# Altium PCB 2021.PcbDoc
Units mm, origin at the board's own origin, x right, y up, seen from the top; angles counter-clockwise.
Board outline 152.4 x 101.6 mm, 2 copper layers (Top Layer, Bottom Layer); 50 components, 31 nets, 124 pads, 3 vias.
Unrouted connection lines stored in the file: 58.
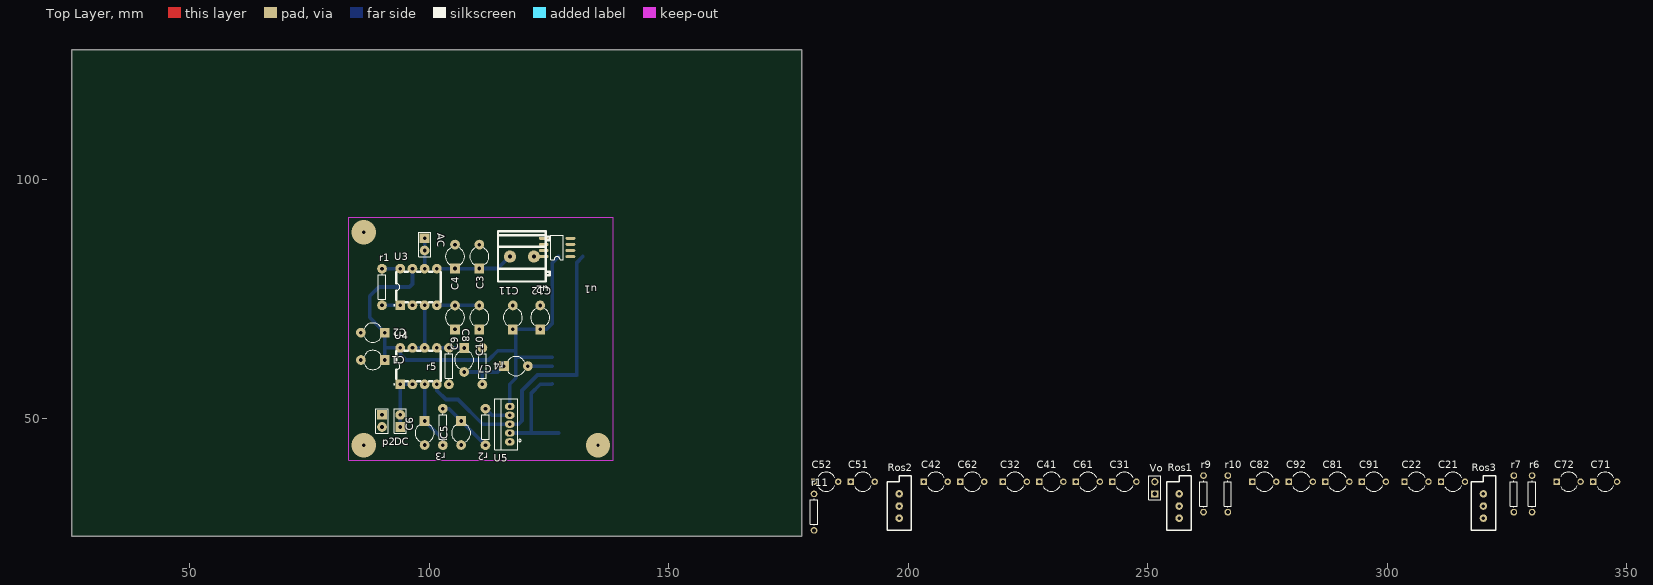
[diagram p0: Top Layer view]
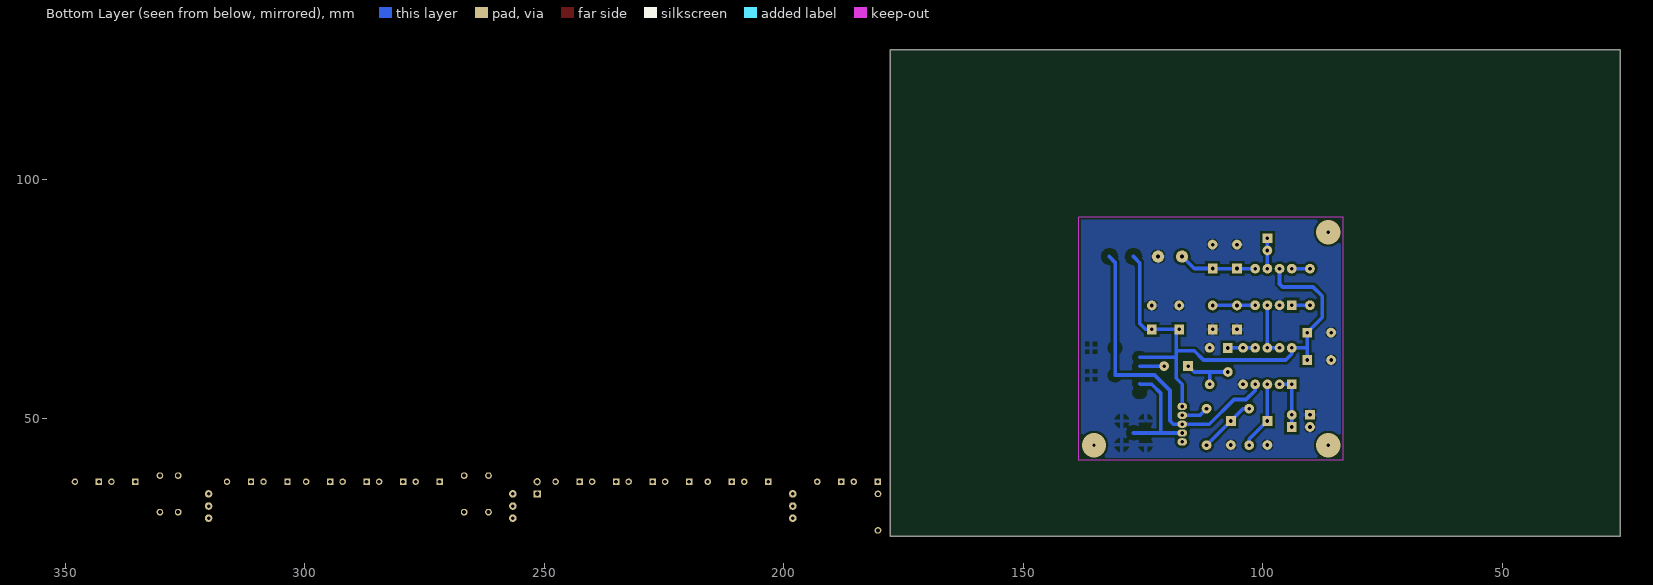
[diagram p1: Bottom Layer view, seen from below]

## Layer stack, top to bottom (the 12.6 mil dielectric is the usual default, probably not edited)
Top Layer: signal copper 0.0356
Dielectric: dielectric 0.32, FR-4, Dk 4.8
Bottom Layer: signal copper 0.0356

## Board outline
25.4,25.4 177.8,25.4 177.8,127 25.4,127

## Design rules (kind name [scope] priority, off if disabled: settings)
Clearance [All] p1: gap=0.508
MinimumSolderMaskSliver [All] p1 off: minsoldermaskwidth=0.254
PolygonConnect [All] p1: connectstyle=Relief reliefconductorwidth=0.762 reliefentries=4 polygonreliefangle="90 Angle"
RoutingVias [All] p1: holewidth=0.711 width=1.27 viastyle="Through Hole" minholewidth=0.711 minwidth=1.27 maxholewidth=0.711 maxwidth=1.27
ShortCircuit [All] p1 off: allowed=FALSE
SilkscreenOverComponentPads [IsPad] p1 off: minsilkscreentomaskgap=0.254
SolderMaskExpansion [All] p1: expansion=0.102
TestPointUsage [All] p1: valid=0 allowmultiple=FALSE
Testpoint [All] p1: side=3 testpointundercomponent=TRUE minsize=1.016 maxsize=2.54 preferedsize=1.524 minholesize=0 maxholesize=1.016 preferedholesize=0.813 testpointgrid=0.025 style=297 order=0-112345678
Width [All] p1: maxlimit=1.27 minlimit=0.762 preferedwidth=0.762
21 further rules are at their usual default settings.

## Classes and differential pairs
component class TPS5403: C1 C2 C3 C4 D1 L P2 R1 R2 R3 U1
component class 2021: AC C5 C6 C7 C8 C9 C10 C11 C12 C21 C22 C31 C32 C41 C42 C51 C52 C61 C62 C71 C72 C81 C82 C91 C92 DC r2 r3 r4 r5 r6 r7 r11 Ros1 Ros2 Ros3 u2 U3 U4 U5 Vo

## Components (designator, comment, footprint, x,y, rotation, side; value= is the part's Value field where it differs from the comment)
AC "Header 2" HDR1X2#1 99.06,87.63 r270 top
C1 "Cap" CAPR5-4X5#1 88.265,62.23 r180 top
C2 "Cap" CAPR5-4X5#1 88.265,67.945 r180 top
C3 "Cap" CAPR5-4X5#1 110.49,83.82 r90 top
C4 "Cap Pol1" CAPR5-4X5#1 105.41,83.82 r90 top
C5 "Cap2" CAPR5-4X5#1 106.68,46.99 r270 top
C6 "Cap2" CAPR5-4X5#1 99.06,46.99 r270 top
C7 "Cap2" CAPR5-4X5#1 118.11,60.96 r0 top
C8 "Cap2" CAPR5-4X5#1 107.315,62.23 r270 top
C9 "Cap2" CAPR5-4X5#1 105.41,71.12 r90 top
C10 "Cap2" CAPR5-4X5#1 110.49,71.12 r90 top
C11 "Cap2" CAPR5-4X5#1 117.475,71.12 r90 top
C12 "Cap2" CAPR5-4X5#1 123.19,71.12 r90 top
C21 "Cap2" CAPR5-4X5#2 313.69,36.83 r0 top
C22 "Cap2" CAPR5-4X5#2 306.07,36.83 r0 top
C31 "Cap2" CAPR5-4X5#2 245.11,36.83 r0 top
C32 "Cap2" CAPR5-4X5#2 222.25,36.83 r0 top
C41 "Cap2" CAPR5-4X5#2 229.87,36.83 r0 top
C42 "Cap2" CAPR5-4X5#2 205.74,36.83 r0 top
C51 "Cap2" CAPR5-4X5#2 190.5,36.83 r0 top
C52 "Cap2" CAPR5-4X5#2 182.88,36.83 r0 top
C61 "Cap2" CAPR5-4X5#2 237.49,36.83 r0 top
C62 "Cap2" CAPR5-4X5#2 213.36,36.83 r0 top
C71 "Cap2" CAPR5-4X5#2 345.44,36.83 r0 top
C72 "Cap2" CAPR5-4X5#2 337.82,36.83 r0 top
C81 "Cap2" CAPR5-4X5#2 289.56,36.83 r0 top
C82 "Cap2" CAPR5-4X5#2 274.32,36.83 r0 top
C91 "Cap2" CAPR5-4X5#2 297.18,36.83 r0 top
C92 "Cap2" CAPR5-4X5#2 281.94,36.83 r0 top
DC "Header 2" HDR1X2#1 93.98,48.26 r90 top
p2 "ENABLE" HDR1X2#1 90.17,50.8 r270 top
r1 "Res2" AXIAL-0.3#1 90.17,77.47 r90 top
r2 "Res2" AXIAL-0.3#1 111.76,48.26 r270 top
r3 "Res2" AXIAL-0.3#1 102.87,48.26 r270 top
r4 "Res1" AXIAL-0.3#1 111.125,60.96 r90 top
r5 "Res1" AXIAL-0.3#1 104.14,60.96 r270 top
r6 "Res1" AXIAL-0.3#2 330.2,34.29 r90 top
r7 "Res1" AXIAL-0.3#2 326.39,34.29 r90 top
r9 "Res1" AXIAL-0.3#2 261.62,34.29 r90 top
r10 "Res1" AXIAL-0.3#2 266.7,34.29 r90 top
r11 "Res1" AXIAL-0.3#2 180.34,30.48 r90 top
Ros1 "POT1" VR5 256.54,29.21 r90 top
Ros2 "POT2" VR5 198.12,29.21 r90 top
Ros3 "POT1" VR5 320.04,29.21 r90 top
u1 "TPS5430" SO-8 129.5,83.82 r180 top
u2 "KF128-5.0-2P" CONN-TH_P5.00_KF128-5.0-2P 119.38,83.82 r180 top
U3 "AD620ANZ" DIP-8_L9.3-W6.4-P2.54-LS7.6-BL 97.79,77.47 r0 top
U4 "opa2727" DIP-8_L9.3-W6.4-P2.54-LS7.6-BL 97.79,60.96 r0 top
U5 "opa2727" TO-220-5L_L10.2-W4.5-P1.71-L 116.84,48.84 r90 top
Vo "Header 2" HDR1X2#2 251.46,34.29 r90 top

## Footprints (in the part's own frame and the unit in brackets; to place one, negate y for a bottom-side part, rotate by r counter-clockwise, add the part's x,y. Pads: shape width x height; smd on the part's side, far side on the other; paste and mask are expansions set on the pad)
AXIAL-0.3#1 [mil] "Resistor; 2 Leads"
  round 80 hole 30: 1(-150,0) 2(150,0)
  silkscreen extent -109,-30 109,30
AXIAL-0.3#2 [mil] "Resistor; 2 Leads"
  round 55.12 hole 33.46: 1(-150,0) 2(150,0)
  silkscreen extent -109,-30 109,30
CAPR5-4X5#1 [mil] "Capacitor; 2 Leads"
  rect 80x80 hole 30: 1(-98.43,0)
  round 80 hole 30: 2(98.43,0)
  silkscreen extent -66,-79 72,79
CAPR5-4X5#2 [mil] "Capacitor; 2 Leads"
  rect 53.15x53.15 hole 31.5: 1(-98.43,0)
  round 53.15 hole 31.5: 2(98.43,0)
  silkscreen extent -66,-79 72,79
CONN-TH_P5.00_KF128-5.0-2P [mm]
  round 2.54 hole 0.813: 1(-2.5,0) 2(2.5,0)
  silkscreen extent -5.76,-5.3 5,5.2
DIP-8_L9.3-W6.4-P2.54-LS7.6-BL [mil]
  rect 80x80 hole 30: 1(-150,-150)
  round 80 hole 30: 2(-50,-150) 3(50,-150) 4(150,-150) 5(150,150) 6(50,150) 7(-50,150) 8(-150,150)
  silkscreen extent -204,-154 183,126
HDR1X2#1 [mil] "Connector; Header; 2 Position"
  rect 80x80 hole 30: 1(0,0)
  round 80 hole 30: 2(100,0)
  silkscreen extent -50,-50 150,50
HDR1X2#2 [mil] "Connector; Header; 2 Position"
  rect 59.06x59.06 hole 35.43: 1(0,0)
  round 59.06 hole 35.43: 2(100,0)
  silkscreen extent -50,-50 150,50
SO-8 [mil]
  oval 80x24 smd: 1(0,0) 2(0,-50) 3(0,-100) 4(0,-150) 5(220,-150) 6(220,-100) 7(220,-50) 8(220,0)
  silkscreen extent 60,-175 160,25
TO-220-5L_L10.2-W4.5-P1.71-L [mil]
  oval 60x80 hole 30: 1(-145.67,0) 2(-72.84,0) 3(0,0) 4(72.84,0) 5(145.67,0)
  silkscreen extent -209,-93 209,125
VR5 [mil]
  round 62 hole 28: 1(0,0) 2(200,0) 3(100,0)
  silkscreen extent -100,-100 350,100

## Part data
AC DC Vo: "Header, 2-Pin"
C1 C2 C3 C4: library part Cap2, "Capacitor"
C5 C6 C7 C8 C9 C10 C11 C12 C21 C22 C31 C32 C41 C42 C51 C52 C61 C62 C71 C72 C81 C82 C91 C92: "Capacitor"
p2: library part "Header 2", "Header, 2-Pin"
r1 r2 r3: library part Res1, "Resistor"
r4 r5 r6 r7 r9 r10 r11: "Resistor"
Ros1 Ros3: "Potentiometer"
Ros2: library part POT1, "Potentiometer"
u1: library part TPS5403, "TPS5403"
U4: library part AD620ANZ
U5: library part LM2596T-12_C194353

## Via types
v1: diameter 5.08, hole 0.711, Top Layer to Bottom Layer, 3 vias

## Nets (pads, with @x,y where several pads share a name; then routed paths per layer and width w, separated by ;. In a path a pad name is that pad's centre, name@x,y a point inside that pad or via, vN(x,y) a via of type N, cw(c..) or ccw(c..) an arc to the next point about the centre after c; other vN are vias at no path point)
+5: C11.1 C12.1 C21.1 C22.1 C41.2 C42.2 C71.1 C72.1 C91.1 C92.1 Ros1.3 Ros2.3 Ros3.3 U3.7 U4.7
-5: C9.1 C10.1 C31.1 C32.1 C51.1 C52.1 C81.1 C82.1 U4.4 U5.5
-5v: C61.1 C62.1 U3.4 | length 75.6
  Bottom Layer w0.762: 101.6,57.15 101.6,55.88 103.505,53.975 106.045,53.975 111.18,48.84 116.84,48.84 118.69,48.84 119.38,49.53 119.38,55.88 122.61,59.11 125.73,59.11 130.755,59.11 130.81,59.055 130.85,59.095 130.85,64.77 130.85,82.59 132.08,83.82 ; U3.4 110.49,73.66
GND: C1.1 C5.2 C6.2 C9.2 C10.2 C11.2 C12.2 C21.2 C22.2 C31.2 C32.2 C41.1 C42.1 C51.2 C52.2 C61.2 C62.2 C71.2 C72.2 C81.2 C82.2 C91.2 C92.2 r4.2 r5.2 r7.1 U3.2
NetAC_1: AC.1 AC.2 U3.3 U4.6
NetC1_2: C1.2 C2.2 u1.7
NetC2_1: C2.1 C4.2 p2.2 r3.1 u1.6
NetC3_1: C3.1 u1.8 | length 16.3
  Bottom Layer w0.762: 101.6,81.28 C3.1@110.49,81.28 ; C3.1 114.34,81.32 116.84,83.82
NetC3_2: C3.2 u1.1
NetC4_1: C4.1 r1.2
NetC5_1: C5.1 r9.2 r10.1 | length 12
  Bottom Layer w0.762: 102.87,52.07 104.14,52.07 111.76,44.45
NetC6_1: C6.1 r10.2 U4.3 | length 14.3
  Bottom Layer w0.762: U4.3 99.06,49.53 102.87,45.72 102.87,44.45
NetC7_1: C7.1 C8.2 r4.1 | length 11.3
  Bottom Layer w0.762: C8.2 114.34,59.73 C7.1@115.57,60.96 ; r4.1 111.125,59.69
NetC7_2: C7.2 r9.1 u2.1 u2.2 | length 5.1
  Bottom Layer w0.762: C7.2@120.65,60.96 125.73,60.96
NetC8_1: C8.1 r5.1 U5.3 | length 5.7
  Bottom Layer w0.762: 101.6,64.77 C8.1@107.315,64.77
NetDC_1: DC.1 DC.2
NetP2_1: p2.1 u1.5
Netr1_1: r1.1 r2.2 | length 3.8
  Bottom Layer w0.762: r1.1 93.98,73.66
Netr2_1: r2.1 r3.2 u1.4 | length 5.7
  Bottom Layer w0.762: r2.1 113.14,50.69 116.84,50.69
Netr6_1: r6.1 r7.2
Netr11_1: r11.1 U3.8
Netr11_2: r11.2 U3.1
NetRos1_1: Ros1.1 U4.1
NetRos1_2: Ros1.2 U4.8
NetRos2_1: Ros2.1 U5.1
NetRos2_2: Ros2.2
NetRos3_1: Ros3.1
NetRos3_2: Ros3.2
NetU3_6: U3.6 Vo.1 Vo.2
VCC: r6.2
VREF: U3.5
pads on no net: u1.2 u1.3 U4.2 U4.5 U5.2 U5.4
copper on no net: | length 161.8
  Bottom Layer w0.762: 90.17,81.28 93.98,81.28 ; 90.765,62.23 90.765,64.77 ; 93.98,48.26 93.98,50.8 93.98,57.15 96.52,57.15 ; 96.52,64.77 99.06,64.77 99.06,73.66 ; 96.52,81.28 96.52,78.105 95.885,77.47 89.535,77.47 87.63,75.565 87.63,71.12 90.805,67.945 90.765,67.905 90.765,64.77 ; 99.06,81.28 99.06,85.09 99.06,87.63 ; 116.84,46.99 121.285,46.99 ; 116.84,52.54 116.84,57.15 118.11,58.42 118.11,62.865 ; 117.515,68.62 123.19,68.62 124.46,68.62 125.73,69.89 125.73,82.55 127,83.82 ; 118.11,68.58 118.11,64.135 ; 125.73,57.26 125.62,57.15 123.19,57.15 121.285,55.245 121.285,46.99 ; 125.73,62.81 118.165,62.81 118.11,62.865 ; 127,46.99 121.285,46.99 ; 90.765,64.77 93.98,64.77 93.98,63.5 95.25,62.23 112.395,62.23 114.3,64.135 118.11,64.135 ; 118.11,62.865 118.11,64.135
  other v1: 86.36,44.45 135.255,44.45 86.36,88.9

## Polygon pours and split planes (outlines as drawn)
GND on Bottom Layer "Top Layer-No Net" (solid, remove dead copper, pour order 0): 83.185,92.075 138.43,92.075 138.43,41.275 83.185,41.275

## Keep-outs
Keep-Out Layer:
  lines w0.1: 83.185,41.275 83.185,92.075 138.43,92.075 138.43,41.275 83.185,41.275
